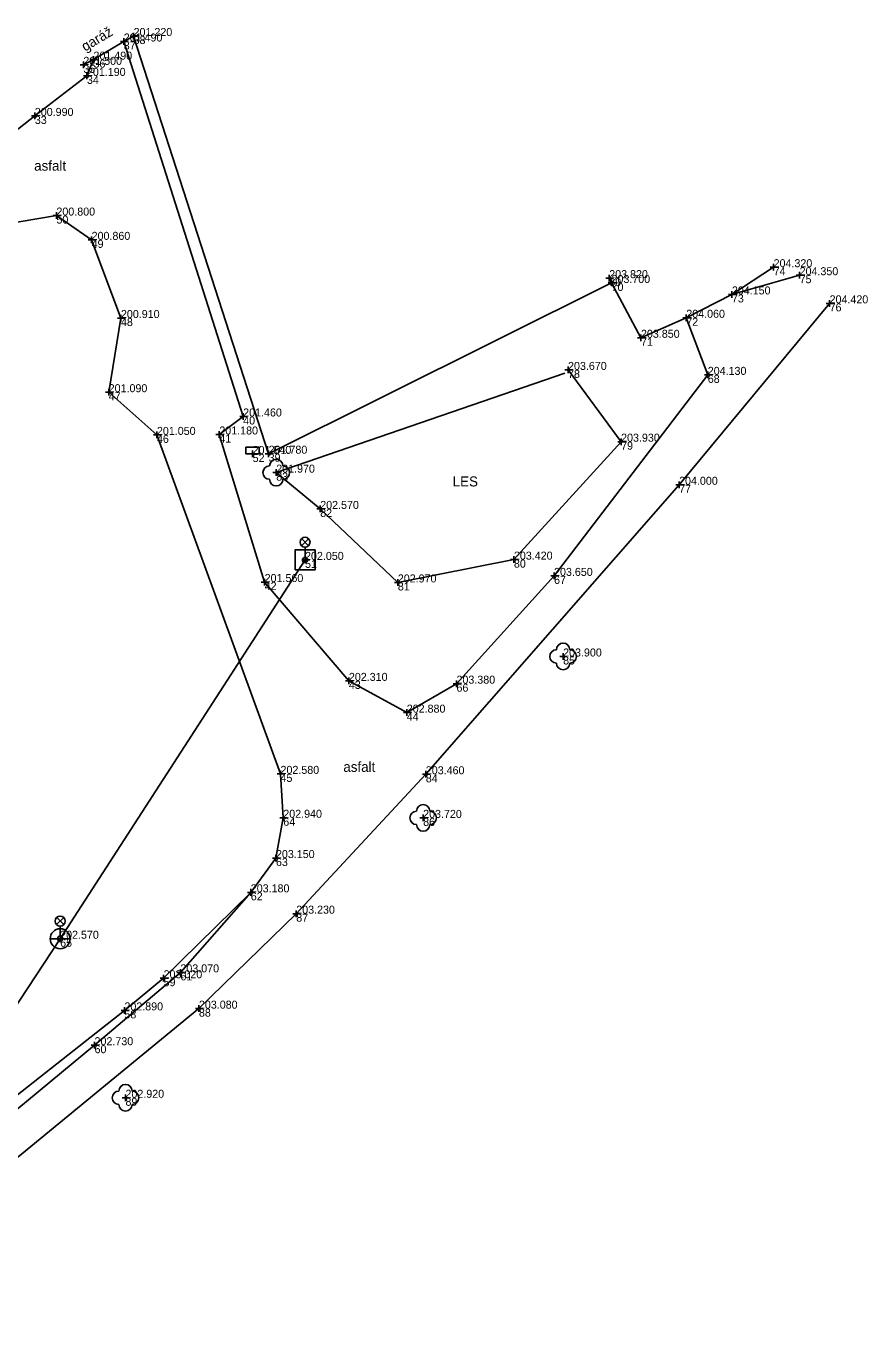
# Model space of a CAD drawing. Extents: x -744883 to -744469, y -966832 to -966374.
# Drawn here: x -744717.1 to -744653.9, y -966471.6 to -966373.5 of the extents above; entities that cross this region are included whole.
import ezdxf

# ---------------------------------------------------------------- set-up
doc = ezdxf.new("R2010")
doc.units = 0
for name, color, linetype in [('Body - výška', 7, 'Continuous'), ('Body - značka', 7, 'Continuous'), ('Body - číslo', 7, 'Continuous'), ('Body polohopisu', 7, 'Continuous'), ('Budovy', 7, 'Continuous'), ('Doplňkové značky', 7, 'Continuous'), ('Ploty_opěrné zdi', 7, 'Continuous'), ('Popisy objektů_povrchů', 7, 'Continuous'), ('Rozhraní ploch', 7, 'Continuous'), ('Stromy_porost', 7, 'Continuous'), ('Vrstva 132', 7, 'Continuous'), ('Vstup na pozemek', 7, 'Continuous'), ('Výšky bodů', 7, 'Continuous'), ('Značky IS', 7, 'Continuous'), ('Čísla bodů', 7, 'Continuous')]:
    doc.layers.add(name, color=color, linetype=linetype)

msp = doc.modelspace()

# ---------------------------------------------------------------- linework, layer by layer
at = {"layer": 'Body - značka'}
for q in [(-744700.32, -966405.57), (-744700.07, -966405.32), (-744699.82, -966405.57), (-744700.07, -966405.82)]:
    msp.add_line((-744700.07, -966405.57), q, dxfattribs=at)
at = {"layer": 'Body polohopisu'}
for p, q in [((-744709, -966374.24), (-744709.25, -966374.24)), ((-744709, -966374.24), (-744709, -966373.99)), ((-744709, -966374.24), (-744708.75, -966374.24)), ((-744709, -966374.24), (-744709, -966374.49)), ((-744709.74, -966374.65), (-744709.99, -966374.65)), ((-744709.74, -966374.65), (-744709.74, -966374.4)), ((-744709.74, -966374.65), (-744709.49, -966374.65)), ((-744709.74, -966374.65), (-744709.74, -966374.9)), ((-744712.77, -966376.4), (-744712.77, -966376.15)), ((-744712.01, -966376.01), (-744712.26, -966376.01)), ((-744712.01, -966376.01), (-744712.01, -966375.76)), ((-744712.01, -966376.01), (-744711.76, -966376.01)), ((-744712.01, -966376.01), (-744712.01, -966376.26)), ((-744712.77, -966376.4), (-744713.02, -966376.4)), ((-744712.77, -966376.4), (-744712.52, -966376.4)), ((-744712.77, -966376.4), (-744712.77, -966376.65)), ((-744712.5, -966377.23), (-744712.75, -966377.23)), ((-744712.5, -966377.23), (-744712.5, -966376.98)), ((-744712.5, -966377.23), (-744712.25, -966377.23)), ((-744712.5, -966377.23), (-744712.5, -966377.48)), ((-744716.41, -966380.23), (-744716.41, -966379.98)), ((-744716.41, -966380.23), (-744716.66, -966380.23)), ((-744716.41, -966380.23), (-744716.16, -966380.23)), ((-744716.41, -966380.23), (-744716.41, -966380.48)), ((-744714.79, -966387.7), (-744715.04, -966387.7)), ((-744714.79, -966387.7), (-744714.79, -966387.45)), ((-744714.79, -966387.7), (-744714.54, -966387.7)), ((-744714.79, -966387.7), (-744714.79, -966387.95)), ((-744712.15, -966389.52), (-744712.4, -966389.52)), ((-744712.15, -966389.52), (-744712.15, -966389.27)), ((-744712.15, -966389.52), (-744711.9, -966389.52)), ((-744712.15, -966389.52), (-744712.15, -966389.77)), ((-744660.99, -966391.57), (-744661.24, -966391.57)), ((-744660.99, -966391.57), (-744660.99, -966391.32)), ((-744660.99, -966391.57), (-744660.74, -966391.57)), ((-744660.99, -966391.57), (-744660.99, -966391.82)), ((-744659.04, -966392.17), (-744659.04, -966391.92)), ((-744673.32, -966392.39), (-744673.57, -966392.39)), ((-744673.15, -966392.75), (-744673.4, -966392.75)), ((-744673.32, -966392.39), (-744673.32, -966392.14)), ((-744673.32, -966392.39), (-744673.07, -966392.39)), ((-744673.32, -966392.39), (-744673.32, -966392.64)), ((-744673.15, -966392.75), (-744673.15, -966392.5)), ((-744673.15, -966392.75), (-744672.9, -966392.75)), ((-744673.15, -966392.75), (-744673.15, -966393)), ((-744659.04, -966392.17), (-744659.29, -966392.17)), ((-744659.04, -966392.17), (-744658.79, -966392.17)), ((-744659.04, -966392.17), (-744659.04, -966392.42)), ((-744664.12, -966393.61), (-744664.37, -966393.61)), ((-744664.12, -966393.61), (-744664.12, -966393.36)), ((-744664.12, -966393.61), (-744663.87, -966393.61)), ((-744664.12, -966393.61), (-744664.12, -966393.86)), ((-744656.79, -966394.28), (-744657.04, -966394.28)), ((-744656.79, -966394.28), (-744656.79, -966394.03)), ((-744656.79, -966394.28), (-744656.54, -966394.28)), ((-744656.79, -966394.28), (-744656.79, -966394.53)), ((-744709.95, -966395.38), (-744710.2, -966395.38)), ((-744709.95, -966395.38), (-744709.95, -966395.13)), ((-744709.95, -966395.38), (-744709.7, -966395.38)), ((-744709.95, -966395.38), (-744709.95, -966395.63)), ((-744667.54, -966395.36), (-744667.79, -966395.36)), ((-744667.54, -966395.36), (-744667.54, -966395.11)), ((-744667.54, -966395.36), (-744667.29, -966395.36)), ((-744667.54, -966395.36), (-744667.54, -966395.61)), ((-744670.94, -966396.86), (-744671.19, -966396.86)), ((-744670.94, -966396.86), (-744670.94, -966396.61)), ((-744670.94, -966396.86), (-744670.69, -966396.86)), ((-744670.94, -966396.86), (-744670.94, -966397.11)), ((-744676.41, -966399.27), (-744676.66, -966399.27)), ((-744676.41, -966399.27), (-744676.41, -966399.02)), ((-744676.41, -966399.27), (-744676.16, -966399.27)), ((-744676.41, -966399.27), (-744676.41, -966399.52)), ((-744665.93, -966399.64), (-744666.18, -966399.64)), ((-744665.93, -966399.64), (-744665.93, -966399.39)), ((-744665.93, -966399.64), (-744665.68, -966399.64)), ((-744665.93, -966399.64), (-744665.93, -966399.89)), ((-744710.87, -966400.94), (-744710.87, -966400.69)), ((-744710.87, -966400.94), (-744711.12, -966400.94)), ((-744710.87, -966400.94), (-744710.62, -966400.94)), ((-744710.87, -966400.94), (-744710.87, -966401.19)), ((-744700.78, -966402.76), (-744701.03, -966402.76)), ((-744700.78, -966402.76), (-744700.78, -966402.51)), ((-744700.78, -966402.76), (-744700.53, -966402.76)), ((-744700.78, -966402.76), (-744700.78, -966403.01)), ((-744707.25, -966404.14), (-744707.5, -966404.14)), ((-744707.25, -966404.14), (-744707.25, -966403.89)), ((-744707.25, -966404.14), (-744707, -966404.14)), ((-744707.25, -966404.14), (-744707.25, -966404.39)), ((-744702.57, -966404.11), (-744702.82, -966404.11)), ((-744702.57, -966404.11), (-744702.57, -966403.86)), ((-744702.57, -966404.11), (-744702.32, -966404.11)), ((-744702.57, -966404.11), (-744702.57, -966404.36)), ((-744672.43, -966404.65), (-744672.68, -966404.65)), ((-744672.43, -966404.65), (-744672.43, -966404.4)), ((-744672.43, -966404.65), (-744672.18, -966404.65)), ((-744672.43, -966404.65), (-744672.43, -966404.9)), ((-744698.87, -966405.55), (-744699.12, -966405.55)), ((-744698.87, -966405.55), (-744698.87, -966405.3)), ((-744698.87, -966405.55), (-744698.62, -966405.55)), ((-744698.87, -966405.55), (-744698.87, -966405.8)), ((-744698.3, -966406.97), (-744698.55, -966406.97)), ((-744698.3, -966406.97), (-744698.3, -966406.72)), ((-744698.3, -966406.97), (-744698.05, -966406.97)), ((-744698.3, -966406.97), (-744698.3, -966407.22)), ((-744668.08, -966407.88), (-744668.08, -966407.63)), ((-744668.08, -966407.88), (-744668.33, -966407.88)), ((-744668.08, -966407.88), (-744667.83, -966407.88)), ((-744668.08, -966407.88), (-744668.08, -966408.13)), ((-744695, -966409.69), (-744695, -966409.44)), ((-744695, -966409.69), (-744695.25, -966409.69)), ((-744695, -966409.69), (-744694.75, -966409.69)), ((-744695, -966409.69), (-744695, -966409.94)), ((-744696.14, -966413.51), (-744696.39, -966413.51)), ((-744696.14, -966413.51), (-744696.14, -966413.26)), ((-744696.14, -966413.51), (-744695.89, -966413.51)), ((-744696.14, -966413.51), (-744696.14, -966413.76)), ((-744680.47, -966413.49), (-744680.72, -966413.49)), ((-744680.47, -966413.49), (-744680.47, -966413.24)), ((-744680.47, -966413.49), (-744680.22, -966413.49)), ((-744680.47, -966413.49), (-744680.47, -966413.74)), ((-744677.46, -966414.71), (-744677.46, -966414.46)), ((-744699.17, -966415.17), (-744699.42, -966415.17)), ((-744699.17, -966415.17), (-744699.17, -966414.92)), ((-744699.17, -966415.17), (-744698.92, -966415.17)), ((-744699.17, -966415.17), (-744699.17, -966415.42)), ((-744689.18, -966415.2), (-744689.43, -966415.2)), ((-744689.18, -966415.2), (-744689.18, -966414.95)), ((-744689.18, -966415.2), (-744688.93, -966415.2)), ((-744689.18, -966415.2), (-744689.18, -966415.45)), ((-744677.46, -966414.71), (-744677.71, -966414.71)), ((-744677.46, -966414.71), (-744677.21, -966414.71)), ((-744677.46, -966414.71), (-744677.46, -966414.96)), ((-744676.78, -966420.75), (-744677.03, -966420.75)), ((-744676.78, -966420.75), (-744676.78, -966420.5)), ((-744676.78, -966420.75), (-744676.53, -966420.75)), ((-744676.78, -966420.75), (-744676.78, -966421)), ((-744692.85, -966422.58), (-744692.85, -966422.33)), ((-744692.85, -966422.58), (-744693.1, -966422.58)), ((-744692.85, -966422.58), (-744692.6, -966422.58)), ((-744692.85, -966422.58), (-744692.85, -966422.83)), ((-744684.78, -966422.79), (-744685.03, -966422.79)), ((-744684.78, -966422.79), (-744684.78, -966422.54)), ((-744684.78, -966422.79), (-744684.53, -966422.79)), ((-744684.78, -966422.79), (-744684.78, -966423.04)), ((-744688.51, -966424.96), (-744688.76, -966424.96)), ((-744688.51, -966424.96), (-744688.51, -966424.71)), ((-744688.51, -966424.96), (-744688.26, -966424.96)), ((-744688.51, -966424.96), (-744688.51, -966425.21)), ((-744697.98, -966429.55), (-744698.23, -966429.55)), ((-744697.98, -966429.55), (-744697.98, -966429.3)), ((-744697.98, -966429.55), (-744697.73, -966429.55)), ((-744697.98, -966429.55), (-744697.98, -966429.8)), ((-744687.08, -966429.58), (-744687.33, -966429.58)), ((-744687.08, -966429.58), (-744687.08, -966429.33)), ((-744687.08, -966429.58), (-744686.83, -966429.58)), ((-744687.08, -966429.58), (-744687.08, -966429.83)), ((-744697.77, -966432.84), (-744698.02, -966432.84)), ((-744697.77, -966432.84), (-744697.77, -966432.59)), ((-744697.77, -966432.84), (-744697.52, -966432.84)), ((-744697.77, -966432.84), (-744697.77, -966433.09)), ((-744687.28, -966432.85), (-744687.53, -966432.85)), ((-744687.28, -966432.85), (-744687.28, -966432.6)), ((-744687.28, -966432.85), (-744687.03, -966432.85)), ((-744687.28, -966432.85), (-744687.28, -966433.1)), ((-744698.32, -966435.86), (-744698.57, -966435.86)), ((-744698.32, -966435.86), (-744698.32, -966435.61)), ((-744698.32, -966435.86), (-744698.07, -966435.86)), ((-744698.32, -966435.86), (-744698.32, -966436.11)), ((-744700.21, -966438.43), (-744700.46, -966438.43)), ((-744700.21, -966438.43), (-744700.21, -966438.18)), ((-744700.21, -966438.43), (-744699.96, -966438.43)), ((-744700.21, -966438.43), (-744700.21, -966438.68)), ((-744696.8, -966440.03), (-744697.05, -966440.03)), ((-744696.8, -966440.03), (-744696.8, -966439.78)), ((-744696.8, -966440.03), (-744696.55, -966440.03)), ((-744696.8, -966440.03), (-744696.8, -966440.28)), ((-744714.51, -966441.91), (-744714.76, -966441.91)), ((-744714.51, -966441.91), (-744714.51, -966441.66)), ((-744714.51, -966441.91), (-744714.26, -966441.91)), ((-744714.51, -966441.91), (-744714.51, -966442.16)), ((-744706.75, -966444.87), (-744707, -966444.87)), ((-744706.75, -966444.87), (-744706.75, -966444.62)), ((-744706.75, -966444.87), (-744706.5, -966444.87)), ((-744706.75, -966444.87), (-744706.75, -966445.12)), ((-744705.49, -966444.43), (-744705.74, -966444.43)), ((-744705.49, -966444.43), (-744705.49, -966444.18)), ((-744705.49, -966444.43), (-744705.24, -966444.43)), ((-744705.49, -966444.43), (-744705.49, -966444.68)), ((-744704.1, -966447.15), (-744704.1, -966446.9)), ((-744709.69, -966447.28), (-744709.94, -966447.28)), ((-744709.69, -966447.28), (-744709.69, -966447.03)), ((-744709.69, -966447.28), (-744709.44, -966447.28)), ((-744709.69, -966447.28), (-744709.69, -966447.53)), ((-744704.1, -966447.15), (-744704.35, -966447.15)), ((-744704.1, -966447.15), (-744703.85, -966447.15)), ((-744704.1, -966447.15), (-744704.1, -966447.4)), ((-744711.93, -966449.89), (-744711.93, -966449.64)), ((-744711.93, -966449.89), (-744712.18, -966449.89)), ((-744711.93, -966449.89), (-744711.68, -966449.89)), ((-744711.93, -966449.89), (-744711.93, -966450.14)), ((-744709.61, -966453.83), (-744709.61, -966453.58)), ((-744709.61, -966453.83), (-744709.86, -966453.83)), ((-744709.61, -966453.83), (-744709.36, -966453.83)), ((-744709.61, -966453.83), (-744709.61, -966454.08))]:
    msp.add_line(p, q, dxfattribs=at)
at = {"layer": 'Budovy'}
for points in [[(-744712.77, -966376.4), (-744712.01, -966376.01), (-744709.74, -966374.65), (-744709, -966374.24)], [(-744673.32, -966392.39), (-744673.15, -966392.75), (-744670.94, -966396.86), (-744667.54, -966395.36), (-744664.12, -966393.61), (-744660.99, -966391.57)]]:
    msp.add_lwpolyline(points, dxfattribs=at)
at = {"layer": 'Doplňkové značky'}
for p, q in [((-744696.404, -966412.448), (-744695.876, -966411.92)), ((-744695.868, -966412.445), (-744696.396, -966411.916)), ((-744696.14, -966412.56), (-744696.14, -966413.31)), ((-744714.774, -966440.848), (-744714.246, -966440.32)), ((-744714.238, -966440.845), (-744714.766, -966440.316)), ((-744714.51, -966440.96), (-744714.51, -966441.71))]:
    msp.add_line(p, q, dxfattribs=at)
for centre, radius in [((-744696.14, -966412.185), 0.375), ((-744696.14, -966413.51), 0.2), ((-744714.51, -966440.585), 0.375), ((-744714.51, -966441.91), 0.2)]:
    msp.add_circle(centre, radius, dxfattribs=at)
at = {"layer": 'Ploty_opěrné zdi'}
for points in [[(-744709, -966374.24), (-744698.87, -966405.55), (-744673.15, -966392.75)], [(-744712.5, -966377.23), (-744712.01, -966376.01)], [(-744733.4, -966386.15), (-744732.56, -966386.87), (-744727.25, -966388.74), (-744716.41, -966380.23)], [(-744710.87, -966400.94), (-744709.95, -966395.38), (-744712.15, -966389.52), (-744714.79, -966387.7), (-744720.55, -966388.68)], [(-744697.98, -966429.55), (-744707.25, -966404.14)], [(-744720.61, -966455.87), (-744720.33, -966455.65), (-744709.69, -966447.28), (-744706.75, -966444.87), (-744700.21, -966438.43), (-744698.32, -966435.86), (-744697.77, -966432.84), (-744697.98, -966429.55)]]:
    msp.add_lwpolyline(points, dxfattribs=at)
at = {"layer": 'Rozhraní ploch'}
for points in [[(-744667.54, -966395.36), (-744665.93, -966399.64), (-744677.46, -966414.71), (-744684.78, -966422.79), (-744688.51, -966424.96), (-744692.85, -966422.58), (-744699.17, -966415.17), (-744702.57, -966404.11), (-744700.78, -966402.76), (-744709.74, -966374.65)], [(-744664.12, -966393.61), (-744659.04, -966392.17)], [(-744656.79, -966394.28), (-744668.08, -966407.88), (-744687.08, -966429.58), (-744696.8, -966440.03), (-744704.1, -966447.15), (-744722.33, -966462.09), (-744727.38, -966466.55), (-744729.52, -966469.63), (-744729.89, -966473.57)], [(-744700.21, -966438.43), (-744705.49, -966444.43), (-744711.93, -966449.89), (-744725.35, -966460.98), (-744729.21, -966464.32), (-744740.73, -966475.43), (-744748.38, -966483.65), (-744749.45, -966482.01)]]:
    msp.add_lwpolyline(points, dxfattribs=at)
at = {"layer": 'Stromy_porost'}
for points in [[(-744676.41, -966399.27), (-744672.43, -966404.65), (-744680.47, -966413.49), (-744689.18, -966415.2), (-744695, -966409.69), (-744698.3, -966406.97)], [(-744698.3, -966406.97), (-744676.66, -966399.52)]]:
    msp.add_lwpolyline(points, dxfattribs=at)
for centre in [(-744698.3, -966406.97), (-744676.78, -966420.75), (-744687.28, -966432.85), (-744709.61, -966453.83)]:
    msp.add_circle(centre, 0.0005, dxfattribs=at)
for centre, start, end in [((-744698.8, -966406.97), 89.99999, 269.99999), ((-744698.3, -966406.47), 0, 179.99999), ((-744697.8, -966406.97), 270, 89.99999), ((-744698.3, -966407.47), 179.99999, 359.99999), ((-744677.28, -966420.75), 89.99999, 269.99999), ((-744676.78, -966420.25), 0, 179.99999), ((-744676.28, -966420.75), 270, 89.99999), ((-744676.78, -966421.25), 179.99999, 359.99999), ((-744687.28, -966432.35), 0, 179.99999), ((-744687.78, -966432.85), 89.99999, 269.99999), ((-744686.78, -966432.85), 270, 89.99999), ((-744687.28, -966433.35), 179.99999, 359.99999), ((-744710.11, -966453.83), 89.99999, 269.99999), ((-744709.61, -966453.33), 0, 179.99999), ((-744709.11, -966453.83), 270, 89.99999), ((-744709.61, -966454.33), 179.99999, 359.99999)]:
    msp.add_arc(centre, 0.5, start, end, dxfattribs=at)
at = {"layer": 'Vrstva 132'}
msp.add_lwpolyline([(-744784.17, -966607.48), (-744776.1, -966571.48), (-744766.46, -966535.83), (-744760.61, -966514.26), (-744741.19, -966482.43), (-744714.51, -966441.91), (-744696.14, -966413.51)], dxfattribs=at)
at = {"layer": 'Vstup na pozemek'}
for points in [[(-744716.41, -966380.23), (-744712.5, -966377.23)], [(-744707.25, -966404.14), (-744710.87, -966400.94)]]:
    msp.add_lwpolyline(points, dxfattribs=at)
at = {"layer": 'Značky IS'}
msp.add_line((-744713.763, -966441.91), (-744715.258, -966441.91), dxfattribs=at)
for points in [[(-744700.57, -966405.57), (-744700.57, -966405.07), (-744699.57, -966405.07), (-744699.57, -966405.57)], [(-744696.89, -966414.26), (-744695.39, -966414.26), (-744695.39, -966412.76), (-744696.89, -966412.76)]]:
    msp.add_lwpolyline(points, close=True, dxfattribs=at)
for start, end in [(0, 180), (180, 0)]:
    msp.add_arc((-744714.51, -966441.91), 0.747, start, end, dxfattribs=at)

# ---------------------------------------------------------------- texts
at = {"layer": 'Body - výška'}
msp.add_text('201.540', height=0.6, dxfattribs=at).set_placement((-744700.07, -966405.57))
at = {"layer": 'Body - číslo'}
msp.add_text('52', height=0.6, dxfattribs=at).set_placement((-744700.07, -966406.17))
at = {"layer": 'Popisy objektů_povrchů'}
msp.add_text('garáž', height=0.75, rotation=30.92662, dxfattribs=at).set_placement((-744712.634, -966375.42))
for s, p in [('asfalt', (-744716.461, -966384.336)), ('LES', (-744685.063, -966408.004)), ('asfalt', (-744693.268, -966429.399))]:
    msp.add_text(s, height=0.75, dxfattribs=at).set_placement(p)
at = {"layer": 'Výšky bodů'}
for s, p in [('201.490', (-744709.74, -966374.65)), ('201.220', (-744709, -966374.24)), ('201.500', (-744712.77, -966376.4)), ('201.490', (-744712.01, -966376.01)), ('201.190', (-744712.5, -966377.23)), ('200.990', (-744716.41, -966380.23)), ('200.800', (-744714.79, -966387.7)), ('200.860', (-744712.15, -966389.52)), ('204.320', (-744660.99, -966391.57)), ('203.820', (-744673.32, -966392.39)), ('204.350', (-744659.04, -966392.17)), ('203.700', (-744673.15, -966392.75)), ('204.150', (-744664.12, -966393.61)), ('204.420', (-744656.79, -966394.28)), ('200.910', (-744709.95, -966395.38)), ('204.060', (-744667.54, -966395.36)), ('203.850', (-744670.94, -966396.86)), ('203.670', (-744676.41, -966399.27)), ('204.130', (-744665.93, -966399.64)), ('201.090', (-744710.87, -966400.94)), ('201.460', (-744700.78, -966402.76)), ('201.050', (-744707.25, -966404.14)), ('201.180', (-744702.57, -966404.11)), ('203.930', (-744672.43, -966404.65)), ('201.780', (-744698.87, -966405.55)), ('201.970', (-744698.3, -966406.97)), ('204.000', (-744668.08, -966407.88)), ('202.570', (-744695, -966409.69)), ('202.050', (-744696.14, -966413.51)), ('203.420', (-744680.47, -966413.49)), ('203.650', (-744677.46, -966414.71)), ('201.560', (-744699.17, -966415.17)), ('202.970', (-744689.18, -966415.2)), ('203.900', (-744676.78, -966420.75)), ('202.310', (-744692.85, -966422.58)), ('203.380', (-744684.78, -966422.79)), ('202.880', (-744688.51, -966424.96)), ('202.580', (-744697.98, -966429.55)), ('203.460', (-744687.08, -966429.58)), ('202.940', (-744697.77, -966432.84)), ('203.720', (-744687.28, -966432.85)), ('203.150', (-744698.32, -966435.86)), ('203.180', (-744700.21, -966438.43)), ('203.230', (-744696.8, -966440.03)), ('202.570', (-744714.51, -966441.91)), ('203.070', (-744705.49, -966444.43)), ('203.020', (-744706.75, -966444.87)), ('202.890', (-744709.69, -966447.28)), ('203.080', (-744704.1, -966447.15)), ('202.730', (-744711.93, -966449.89)), ('202.920', (-744709.61, -966453.83))]:
    msp.add_text(s, height=0.6, dxfattribs=at).set_placement(p)
at = {"layer": 'Čísla bodů'}
for s, p in [('38', (-744709, -966374.84)), ('37', (-744709.74, -966375.25)), ('36', (-744712.01, -966376.61)), ('35', (-744712.77, -966377)), ('34', (-744712.5, -966377.83)), ('33', (-744716.41, -966380.83)), ('50', (-744714.79, -966388.3)), ('49', (-744712.15, -966390.12)), ('74', (-744660.99, -966392.17)), ('69', (-744673.32, -966392.99)), ('70', (-744673.15, -966393.35)), ('75', (-744659.04, -966392.77)), ('73', (-744664.12, -966394.21)), ('76', (-744656.79, -966394.88)), ('48', (-744709.95, -966395.98)), ('72', (-744667.54, -966395.96)), ('71', (-744670.94, -966397.46)), ('78', (-744676.41, -966399.87)), ('68', (-744665.93, -966400.24)), ('47', (-744710.87, -966401.54)), ('40', (-744700.78, -966403.36)), ('46', (-744707.25, -966404.74)), ('41', (-744702.57, -966404.71)), ('79', (-744672.43, -966405.25)), ('39', (-744698.87, -966406.15)), ('83', (-744698.3, -966407.57)), ('77', (-744668.08, -966408.48)), ('82', (-744695, -966410.29)), ('51', (-744696.14, -966414.11)), ('80', (-744680.47, -966414.09)), ('42', (-744699.17, -966415.77)), ('81', (-744689.18, -966415.8)), ('67', (-744677.46, -966415.31)), ('85', (-744676.78, -966421.35)), ('43', (-744692.85, -966423.18)), ('66', (-744684.78, -966423.39)), ('44', (-744688.51, -966425.56)), ('45', (-744697.98, -966430.15)), ('84', (-744687.08, -966430.18)), ('64', (-744697.77, -966433.44)), ('86', (-744687.28, -966433.45)), ('63', (-744698.32, -966436.46)), ('62', (-744700.21, -966439.03)), ('87', (-744696.8, -966440.63)), ('65', (-744714.51, -966442.51)), ('59', (-744706.75, -966445.47)), ('61', (-744705.49, -966445.03)), ('58', (-744709.69, -966447.88)), ('88', (-744704.1, -966447.75)), ('60', (-744711.93, -966450.49)), ('89', (-744709.61, -966454.43))]:
    msp.add_text(s, height=0.6, dxfattribs=at).set_placement(p)

doc.saveas('drawing.dxf')
